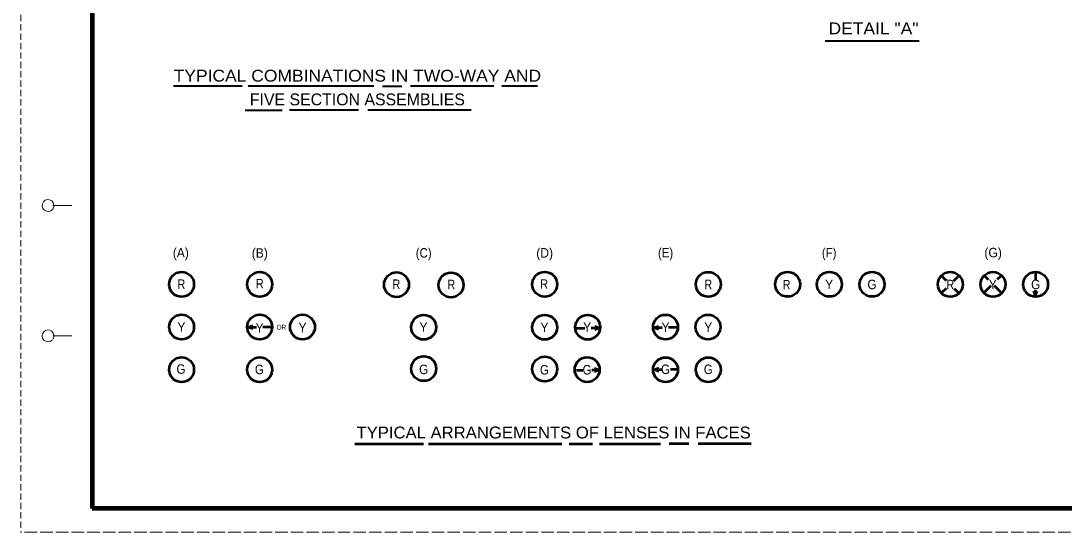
# Model space of a CAD drawing. Extents: x -295 to 385, y -102 to 338.
# Drawn here: x -295.3 to 144.5, y -101.6 to 114.2 of the extents above; entities that cross this region are included whole.
import ezdxf
from ezdxf.enums import TextEntityAlignment as Align

# ---------------------------------------------------------------- set-up
doc = ezdxf.new("R2010")
doc.units = 0
doc.header["$LTSCALE"] = 0.88
doc.linetypes.add('LONG_DASHED', pattern=[7.5, 6, -1.5])
doc.linetypes.add('MEDIUM_DASHED', pattern=[4.5, 3, -1.5])
doc.layers.add('1', color=7, linetype='Continuous', lineweight=53)
doc.layers.add('61', color=7, linetype='Continuous', lineweight=35)

msp = doc.modelspace()

# ---------------------------------------------------------------- linework, layer by layer
at = {"layer": '1', "linetype": 'MEDIUM_DASHED', "lineweight": 13}
msp.add_line((-295.2093, 338.4444), (-295.2693, -101.5956), dxfattribs=at)
at = {"layer": '1', "lineweight": 40}
for p, q in [((43.6896, 105.7107), (83.3247, 105.7107)), ((-230.8821, 86.7623), (-202.0604, 86.7623)), ((-199.4408, 86.7623), (-146.527, 86.7623)), ((-142.7811, 86.5985), (-134.742, 86.5985)), ((-130.9907, 86.7623), (-95.928, 86.7623)), ((-92.5078, 86.7623), (-77.4413, 86.7623)), ((-200.7508, 76.4423), (-185.1803, 76.4423)), ((-182.0827, 76.6061), (-152.9174, 76.6061)), ((-149.0038, 76.6061), (-105.4295, 76.6061))]:
    msp.add_line(p, q, dxfattribs=at)
at = {"layer": '1'}
for p, q in [((94.896, 4.4911), (93.1037, 6.2975)), ((97.9239, 4.4322), (99.8252, 6.3261)), ((112.544, 4.888), (110.9383, 6.5062)), ((116.3446, 5.0907), (117.8692, 6.6094)), ((132.4412, 7.7828), (132.4412, 4.9582)), ((93.0885, -0.3843), (94.8937, 1.4138)), ((99.782, -0.4333), (98.2815, 1.0789)), ((110.9184, -0.3142), (113.6807, 2.4372)), ((117.8649, -0.4748), (115.0618, 2.3503)), ((132.4412, -1.8223), (131.7572, 0.0571)), ((132.4412, -1.8223), (132.4412, 0.5217)), ((132.4412, -1.8223), (133.1252, 0.0571)), ((-199.3162, -15.0457), (-197.4367, -14.3617)), ((-199.3162, -15.0457), (-195.9028, -15.0457)), ((-199.3162, -15.0457), (-197.4367, -15.7297)), ((-189.8162, -15.0457), (-193.3162, -15.0457)), ((-61.0023, -15.5187), (-57.5023, -15.5187)), ((-51.5023, -15.5187), (-54.9157, -15.5187)), ((-51.5023, -15.5187), (-53.3817, -14.8347)), ((-51.5023, -15.5187), (-53.3817, -16.2027)), ((-28.3594, -15.3018), (-26.48, -14.6177)), ((-28.3594, -15.3018), (-24.9461, -15.3018)), ((-28.3594, -15.3018), (-26.48, -15.9857)), ((-18.8594, -15.3018), (-22.3594, -15.3018)), ((-61.0947, -33.2663), (-58.3733, -33.2663)), ((-51.5947, -33.2663), (-54.5546, -33.2663)), ((-51.5947, -33.2663), (-53.4741, -32.5823)), ((-51.5947, -33.2663), (-53.4741, -33.9503)), ((-28.1802, -32.9627), (-26.3008, -32.2787)), ((-28.1802, -32.9627), (-25.2203, -32.9627)), ((-28.1802, -32.9627), (-26.3008, -33.6467)), ((-18.6803, -32.9627), (-21.4016, -32.9627)), ((-154.4503, -64.3768), (-125.5694, -64.3768)), ((-123.4929, -64.3768), (-67.3007, -64.3768)), ((-64.1796, -64.3768), (-54.2907, -64.3768)), ((-51.4324, -64.3768), (-25.6662, -64.3768)), ((-22.0359, -64.1166), (-13.7072, -64.1166)), ((-9.8091, -64.1166), (12.565, -64.1166))]:
    msp.add_line(p, q, dxfattribs=at)
for centre in [(-227.5437, 2.9481), (-194.5662, 2.9481), (-136.934, 2.8362), (-113.9609, 2.7128), (-74.4649, 3.0081), (-5.5471, 2.9267), (27.8974, 3.0216), (45.5198, 3.0216), (63.5211, 3.0216), (96.46, 2.9617), (114.4839, 2.9617), (132.4195, 2.9617), (-227.5437, -15.0456), (-194.5662, -15.0456), (-176.5594, -15.0411), (-125.4519, -15.1116), (-74.4649, -15.1116), (-56.3511, -15.1116), (-23.5484, -15.0803), (-5.6418, -15.0803), (-227.5437, -33.0392), (-194.5662, -33.0392), (-125.4519, -32.5602), (-74.4649, -32.7839), (-56.5748, -33.0076), (-23.5484, -33.0875), (-5.5471, -33.0875)]:
    msp.add_circle(centre, 5.25, dxfattribs=at)
at = {"layer": '61', "lineweight": 13}
for p, q in [((-281.7893, 36.2644), (-273.7893, 36.2644)), ((-281.7693, -18.7556), (-273.7893, -18.7556))]:
    msp.add_line(p, q, dxfattribs=at)
at = {"layer": '61', "lineweight": 158}
msp.add_line((373.8507, -91.5956), (-265.2093, -91.5756), dxfattribs=at)
at = {"layer": '61', "linetype": 'LONG_DASHED', "lineweight": 13}
msp.add_line((384.7907, -101.5756), (-295.2693, -101.5956), dxfattribs=at)
at = {"layer": '61', "lineweight": 158}
msp.add_lwpolyline([(373.8307, 328.4444), (-265.2093, 328.4444), (-265.2093, -91.5756)], dxfattribs=at)
at = {"layer": '61', "lineweight": 13}
for centre, start, end in [((-283.7916, 36.2457), 322.67175, 321.71615), ((-283.7916, -18.7543), 323.13009, 312.31439)]:
    msp.add_arc(centre, 2.5, start, end, dxfattribs=at)

# ---------------------------------------------------------------- texts
at = {"layer": '1'}
for s, height, width, p in [('DETAIL "A"', 5, 1.1, (64.1149, 108.4753)), ('TYPICAL COMBINATIONS IN TWO-WAY AND', 5, 1.1, (-153.4248, 88.5094)), ('(A)', 4, 0.95, (-227.857, 14.342)), ('(B)', 4, 0.95, (-194.5602, 14.1935)), ('(C)', 4, 0.9, (-125.4772, 14.2519)), ('(D)', 4, 0.95, (-74.4875, 14.252)), ('(E)', 4, 0.9, (-23.5102, 14.3104)), ('(F)', 4, 0.9, (45.4307, 14.3034)), ('(G)', 4, 0.95, (114.5417, 14.3762)), ('R', 4, 0.85, (-136.9872, 1.0222)), ('R', 4, 0.85, (-113.8276, 0.8987)), ('R', 4, 0.85, (-74.6982, 1.1101)), ('R', 4, 0.85, (-5.5404, 0.933)), ('R', 4, 0.85, (27.4555, 0.8506)), ('Y', 4, 0.95, (45.4294, 0.9444)), ('G', 4, 0.9, (63.4502, 0.9444)), ('R', 4, 0.85, (96.4533, 0.8967)), ('Y', 4, 0.95, (114.4017, 0.9422)), ('G', 4, 0.9, (132.441, 0.9422)), ('Y', 4, 0.95, (-125.5721, -17.0486)), ('Y', 4, 0.95, (-56.5802, -17.0758)), ('Y', 4, 0.95, (-23.5424, -17.0748)), ('Y', 4, 0.95, (-5.5405, -17.0748)), ('OR', 2, 0.85, (-185.4502, -16.1117)), ('Y', 4, 0.95, (-74.5741, -17.1999)), ('G', 4, 0.9, (-125.5088, -34.9112)), ('G', 4, 0.9, (-74.5741, -35.0756)), ('G', 4, 0.9, (-56.6423, -35.0756)), ('G', 4, 0.9, (-23.5424, -34.8826)), ('G', 4, 0.9, (-5.5405, -34.8826)), ('TYPICAL ARRANGEMENTS OF LENSES IN FACES', 5, 1.05, (-70.7038, -62.0494))]:
    msp.add_text(s, height=height, dxfattribs=dict(at, width=width)).set_placement(p, align=Align.CENTER)
msp.add_text('FIVE SECTION ASSEMBLIES', height=5, dxfattribs=at).set_placement((-153.4248, 78.5094), align=Align.CENTER)
for s, width, p in [('R', 0.85, (-229.2361, 1.0344)), ('R', 0.85, (-196.2047, 1.2396)), ('Y', 0.95, (-229.2972, -17.0392)), ('Y', 0.95, (-196.3562, -17.4168)), ('Y', 0.95, (-178.231, -17.2276)), ('G', 0.9, (-229.6732, -34.776)), ('G', 0.9, (-196.609, -34.9323))]:
    msp.add_text(s, height=4, dxfattribs=dict(at, width=width)).set_placement(p)

doc.saveas('drawing.dxf')
